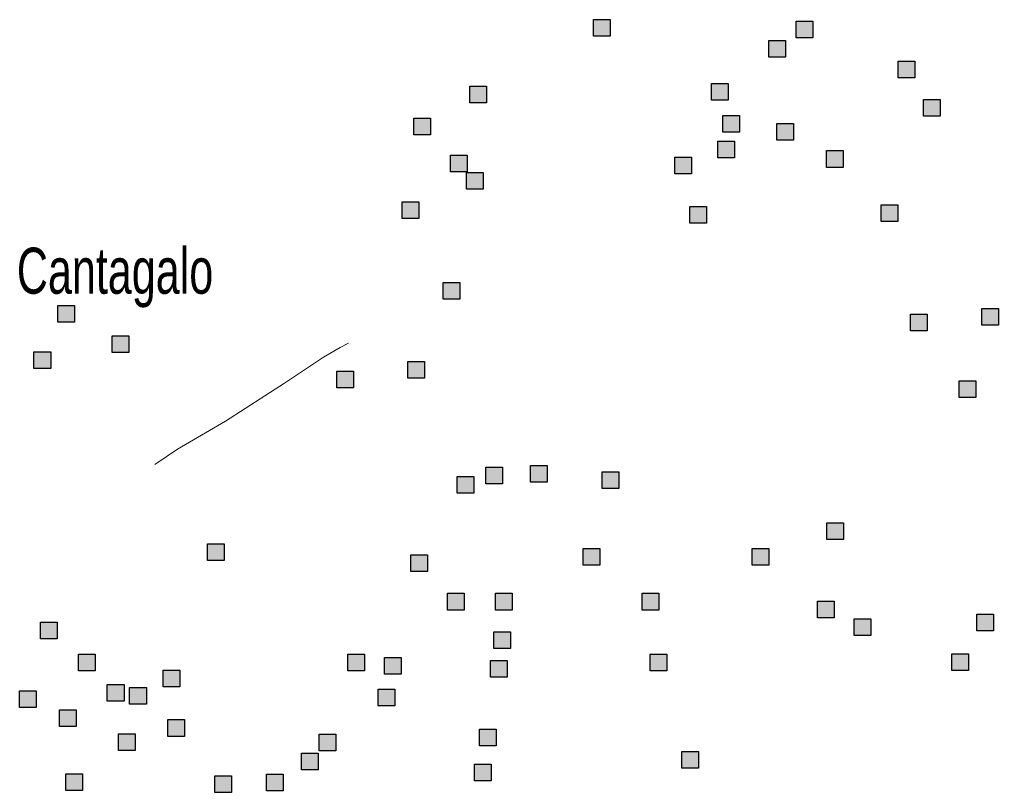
# Model space of a CAD drawing. Extents: x 445.6 to 500, y 8618.1 to 8673.4.
# Drawn here: x 476.597 to 479.999, y 8623.542 to 8626.229 of the extents above; entities that cross this region are included whole.
import ezdxf

# ---------------------------------------------------------------- set-up
doc = ezdxf.new("R2010")
doc.units = 0
doc.header["$LTSCALE"] = 0.064
doc.linetypes.add('DOT_DASHED', pattern=[7.7, 5, -1.2, 0.3, -1.2])
doc.layers.add('2', color=7, linetype='Continuous', lineweight=25)
doc.layers.add('22', color=7, linetype='DOT_DASHED', lineweight=13)
doc.layers.add('61', color=7, linetype='Continuous')

msp = doc.modelspace()

# ---------------------------------------------------------------- hatches: boundary and pattern name
at = {"layer": '2'}
for points in [[(478.592, 8626.2293), (478.65, 8626.2293), (478.65, 8626.1713), (478.592, 8626.1713)], [(479.2958, 8626.2237), (479.3538, 8626.2237), (479.3538, 8626.1657), (479.2958, 8626.1657)], [(479.2016, 8626.157), (479.2596, 8626.157), (479.2596, 8626.099), (479.2016, 8626.099)], [(479.6504, 8626.0848), (479.7084, 8626.0848), (479.7084, 8626.0268), (479.6504, 8626.0268)], [(479.0021, 8626.007), (479.0601, 8626.007), (479.0601, 8625.949), (479.0021, 8625.949)], [(478.1614, 8625.9974), (478.2194, 8625.9974), (478.2194, 8625.9394), (478.1614, 8625.9394)], [(479.7391, 8625.9514), (479.7971, 8625.9514), (479.7971, 8625.8934), (479.7391, 8625.8934)], [(477.9674, 8625.8863), (478.0254, 8625.8863), (478.0254, 8625.8283), (477.9674, 8625.8283)], [(479.0408, 8625.8958), (479.0988, 8625.8958), (479.0988, 8625.8378), (479.0408, 8625.8378)], [(479.2293, 8625.868), (479.2873, 8625.868), (479.2873, 8625.81), (479.2293, 8625.81)], [(479.0242, 8625.8069), (479.0822, 8625.8069), (479.0822, 8625.7489), (479.0242, 8625.7489)], [(479.4011, 8625.7735), (479.4591, 8625.7735), (479.4591, 8625.7155), (479.4011, 8625.7155)], [(478.0949, 8625.7584), (478.1529, 8625.7584), (478.1529, 8625.7004), (478.0949, 8625.7004)], [(478.8746, 8625.7513), (478.9326, 8625.7513), (478.9326, 8625.6933), (478.8746, 8625.6933)], [(478.1503, 8625.6973), (478.2083, 8625.6973), (478.2083, 8625.6393), (478.1503, 8625.6393)], [(477.9264, 8625.5959), (477.9844, 8625.5959), (477.9844, 8625.5379), (477.9264, 8625.5379)], [(478.9262, 8625.5795), (478.9842, 8625.5795), (478.9842, 8625.5215), (478.9262, 8625.5215)], [(479.5912, 8625.585), (479.6492, 8625.585), (479.6492, 8625.527), (479.5912, 8625.527)], [(478.0688, 8625.3154), (478.1268, 8625.3154), (478.1268, 8625.2574), (478.0688, 8625.2574)], [(476.7302, 8625.235), (476.7882, 8625.235), (476.7882, 8625.177), (476.7302, 8625.177)], [(479.9412, 8625.2246), (479.9992, 8625.2246), (479.9992, 8625.1666), (479.9412, 8625.1666)], [(479.6931, 8625.2045), (479.7511, 8625.2045), (479.7511, 8625.1465), (479.6931, 8625.1465)], [(476.9186, 8625.1294), (476.9766, 8625.1294), (476.9766, 8625.0714), (476.9186, 8625.0714)], [(476.6471, 8625.0738), (476.7051, 8625.0738), (476.7051, 8625.0158), (476.6471, 8625.0158)], [(477.9459, 8625.0403), (478.0039, 8625.0403), (478.0039, 8624.9823), (477.9459, 8624.9823)], [(477.6992, 8625.0068), (477.7572, 8625.0068), (477.7572, 8624.9488), (477.6992, 8624.9488)], [(479.8627, 8624.9736), (479.9207, 8624.9736), (479.9207, 8624.9156), (479.8627, 8624.9156)], [(478.2174, 8624.6735), (478.2754, 8624.6735), (478.2754, 8624.6155), (478.2174, 8624.6155)], [(478.3726, 8624.679), (478.4306, 8624.679), (478.4306, 8624.621), (478.3726, 8624.621)], [(478.6219, 8624.6568), (478.6799, 8624.6568), (478.6799, 8624.5988), (478.6219, 8624.5988)], [(478.1177, 8624.6401), (478.1757, 8624.6401), (478.1757, 8624.5821), (478.1177, 8624.5821)], [(479.4033, 8624.479), (479.4613, 8624.479), (479.4613, 8624.421), (479.4033, 8624.421)], [(477.2504, 8624.4065), (477.3084, 8624.4065), (477.3084, 8624.3485), (477.2504, 8624.3485)], [(478.5554, 8624.39), (478.6134, 8624.39), (478.6134, 8624.332), (478.5554, 8624.332)], [(479.1429, 8624.39), (479.2009, 8624.39), (479.2009, 8624.332), (479.1429, 8624.332)], [(477.9569, 8624.3678), (478.0149, 8624.3678), (478.0149, 8624.3098), (477.9569, 8624.3098)], [(478.0844, 8624.2344), (478.1424, 8624.2344), (478.1424, 8624.1764), (478.0844, 8624.1764)], [(478.2507, 8624.2344), (478.3087, 8624.2344), (478.3087, 8624.1764), (478.2507, 8624.1764)], [(478.7605, 8624.2344), (478.8185, 8624.2344), (478.8185, 8624.1764), (478.7605, 8624.1764)], [(479.3701, 8624.2066), (479.4281, 8624.2066), (479.4281, 8624.1486), (479.3701, 8624.1486)], [(479.4975, 8624.1455), (479.5555, 8624.1455), (479.5555, 8624.0875), (479.4975, 8624.0875)], [(479.9237, 8624.1621), (479.9817, 8624.1621), (479.9817, 8624.1041), (479.9237, 8624.1041)], [(476.6692, 8624.1345), (476.7272, 8624.1345), (476.7272, 8624.0765), (476.6692, 8624.0765)], [(478.2451, 8624.101), (478.3031, 8624.101), (478.3031, 8624.043), (478.2451, 8624.043)], [(476.8022, 8624.0233), (476.8602, 8624.0233), (476.8602, 8623.9653), (476.8022, 8623.9653)], [(477.738, 8624.023), (477.796, 8624.023), (477.796, 8623.965), (477.738, 8623.965)], [(477.8655, 8624.0118), (477.9235, 8624.0118), (477.9235, 8623.9538), (477.8655, 8623.9538)], [(478.234, 8624.001), (478.292, 8624.001), (478.292, 8623.943), (478.234, 8623.943)], [(478.7882, 8624.0232), (478.8462, 8624.0232), (478.8462, 8623.9652), (478.7882, 8623.9652)], [(479.8369, 8624.0237), (479.8949, 8624.0237), (479.8949, 8623.9657), (479.8369, 8623.9657)], [(477.0959, 8623.9677), (477.1539, 8623.9677), (477.1539, 8623.9097), (477.0959, 8623.9097)], [(476.902, 8623.9177), (476.96, 8623.9177), (476.96, 8623.8597), (476.902, 8623.8597)], [(476.9796, 8623.9066), (477.0376, 8623.9066), (477.0376, 8623.8486), (476.9796, 8623.8486)], [(477.8433, 8623.9007), (477.9013, 8623.9007), (477.9013, 8623.8427), (477.8433, 8623.8427)], [(476.5972, 8623.8955), (476.6552, 8623.8955), (476.6552, 8623.8375), (476.5972, 8623.8375)], [(476.7357, 8623.8288), (476.7937, 8623.8288), (476.7937, 8623.7708), (476.7357, 8623.7708)], [(477.1118, 8623.7951), (477.1698, 8623.7951), (477.1698, 8623.7371), (477.1118, 8623.7371)], [(478.1952, 8623.762), (478.2532, 8623.762), (478.2532, 8623.704), (478.1952, 8623.704)], [(476.9408, 8623.7454), (476.9988, 8623.7454), (476.9988, 8623.6874), (476.9408, 8623.6874)], [(477.6383, 8623.7451), (477.6963, 8623.7451), (477.6963, 8623.6871), (477.6383, 8623.6871)], [(477.5773, 8623.6784), (477.6353, 8623.6784), (477.6353, 8623.6204), (477.5773, 8623.6204)], [(478.899, 8623.6841), (478.957, 8623.6841), (478.957, 8623.6261), (478.899, 8623.6261)], [(478.1786, 8623.6405), (478.2366, 8623.6405), (478.2366, 8623.5825), (478.1786, 8623.5825)], [(476.7579, 8623.6064), (476.8159, 8623.6064), (476.8159, 8623.5484), (476.7579, 8623.5484)], [(477.2752, 8623.6001), (477.3332, 8623.6001), (477.3332, 8623.5421), (477.2752, 8623.5421)], [(477.4554, 8623.6061), (477.5134, 8623.6061), (477.5134, 8623.5481), (477.4554, 8623.5481)]]:
    msp.add_hatch(color=256, dxfattribs=at).paths.add_polyline_path(points)

# ---------------------------------------------------------------- linework, layer by layer
for points in [[(478.592, 8626.2293), (478.65, 8626.2293), (478.65, 8626.1713), (478.592, 8626.1713)], [(479.2958, 8626.2237), (479.3538, 8626.2237), (479.3538, 8626.1657), (479.2958, 8626.1657)], [(479.2016, 8626.157), (479.2596, 8626.157), (479.2596, 8626.099), (479.2016, 8626.099)], [(479.6504, 8626.0848), (479.7084, 8626.0848), (479.7084, 8626.0268), (479.6504, 8626.0268)], [(479.0021, 8626.007), (479.0601, 8626.007), (479.0601, 8625.949), (479.0021, 8625.949)], [(478.1614, 8625.9974), (478.2194, 8625.9974), (478.2194, 8625.9394), (478.1614, 8625.9394)], [(479.7391, 8625.9514), (479.7971, 8625.9514), (479.7971, 8625.8934), (479.7391, 8625.8934)], [(477.9674, 8625.8863), (478.0254, 8625.8863), (478.0254, 8625.8283), (477.9674, 8625.8283)], [(479.0408, 8625.8958), (479.0988, 8625.8958), (479.0988, 8625.8378), (479.0408, 8625.8378)], [(479.2293, 8625.868), (479.2873, 8625.868), (479.2873, 8625.81), (479.2293, 8625.81)], [(479.0242, 8625.8069), (479.0822, 8625.8069), (479.0822, 8625.7489), (479.0242, 8625.7489)], [(479.4011, 8625.7735), (479.4591, 8625.7735), (479.4591, 8625.7155), (479.4011, 8625.7155)], [(478.0949, 8625.7584), (478.1529, 8625.7584), (478.1529, 8625.7004), (478.0949, 8625.7004)], [(478.8746, 8625.7513), (478.9326, 8625.7513), (478.9326, 8625.6933), (478.8746, 8625.6933)], [(478.1503, 8625.6973), (478.2083, 8625.6973), (478.2083, 8625.6393), (478.1503, 8625.6393)], [(477.9264, 8625.5959), (477.9844, 8625.5959), (477.9844, 8625.5379), (477.9264, 8625.5379)], [(478.9262, 8625.5795), (478.9842, 8625.5795), (478.9842, 8625.5215), (478.9262, 8625.5215)], [(479.5912, 8625.585), (479.6492, 8625.585), (479.6492, 8625.527), (479.5912, 8625.527)], [(478.0688, 8625.3154), (478.1268, 8625.3154), (478.1268, 8625.2574), (478.0688, 8625.2574)], [(476.7302, 8625.235), (476.7882, 8625.235), (476.7882, 8625.177), (476.7302, 8625.177)], [(479.9412, 8625.2246), (479.9992, 8625.2246), (479.9992, 8625.1666), (479.9412, 8625.1666)], [(479.6931, 8625.2045), (479.7511, 8625.2045), (479.7511, 8625.1465), (479.6931, 8625.1465)], [(476.9186, 8625.1294), (476.9766, 8625.1294), (476.9766, 8625.0714), (476.9186, 8625.0714)], [(476.6471, 8625.0738), (476.7051, 8625.0738), (476.7051, 8625.0158), (476.6471, 8625.0158)], [(477.9459, 8625.0403), (478.0039, 8625.0403), (478.0039, 8624.9823), (477.9459, 8624.9823)], [(477.6992, 8625.0068), (477.7572, 8625.0068), (477.7572, 8624.9488), (477.6992, 8624.9488)], [(479.8627, 8624.9736), (479.9207, 8624.9736), (479.9207, 8624.9156), (479.8627, 8624.9156)], [(478.2174, 8624.6735), (478.2754, 8624.6735), (478.2754, 8624.6155), (478.2174, 8624.6155)], [(478.3726, 8624.679), (478.4306, 8624.679), (478.4306, 8624.621), (478.3726, 8624.621)], [(478.6219, 8624.6568), (478.6799, 8624.6568), (478.6799, 8624.5988), (478.6219, 8624.5988)], [(478.1177, 8624.6401), (478.1757, 8624.6401), (478.1757, 8624.5821), (478.1177, 8624.5821)], [(479.4033, 8624.479), (479.4613, 8624.479), (479.4613, 8624.421), (479.4033, 8624.421)], [(477.2504, 8624.4065), (477.3084, 8624.4065), (477.3084, 8624.3485), (477.2504, 8624.3485)], [(478.5554, 8624.39), (478.6134, 8624.39), (478.6134, 8624.332), (478.5554, 8624.332)], [(479.1429, 8624.39), (479.2009, 8624.39), (479.2009, 8624.332), (479.1429, 8624.332)], [(477.9569, 8624.3678), (478.0149, 8624.3678), (478.0149, 8624.3098), (477.9569, 8624.3098)], [(478.0844, 8624.2344), (478.1424, 8624.2344), (478.1424, 8624.1764), (478.0844, 8624.1764)], [(478.2507, 8624.2344), (478.3087, 8624.2344), (478.3087, 8624.1764), (478.2507, 8624.1764)], [(478.7605, 8624.2344), (478.8185, 8624.2344), (478.8185, 8624.1764), (478.7605, 8624.1764)], [(479.3701, 8624.2066), (479.4281, 8624.2066), (479.4281, 8624.1486), (479.3701, 8624.1486)], [(479.4975, 8624.1455), (479.5555, 8624.1455), (479.5555, 8624.0875), (479.4975, 8624.0875)], [(479.9237, 8624.1621), (479.9817, 8624.1621), (479.9817, 8624.1041), (479.9237, 8624.1041)], [(476.6692, 8624.1345), (476.7272, 8624.1345), (476.7272, 8624.0765), (476.6692, 8624.0765)], [(478.2451, 8624.101), (478.3031, 8624.101), (478.3031, 8624.043), (478.2451, 8624.043)], [(476.8022, 8624.0233), (476.8602, 8624.0233), (476.8602, 8623.9653), (476.8022, 8623.9653)], [(477.738, 8624.023), (477.796, 8624.023), (477.796, 8623.965), (477.738, 8623.965)], [(477.8655, 8624.0118), (477.9235, 8624.0118), (477.9235, 8623.9538), (477.8655, 8623.9538)], [(478.234, 8624.001), (478.292, 8624.001), (478.292, 8623.943), (478.234, 8623.943)], [(478.7882, 8624.0232), (478.8462, 8624.0232), (478.8462, 8623.9652), (478.7882, 8623.9652)], [(479.8369, 8624.0237), (479.8949, 8624.0237), (479.8949, 8623.9657), (479.8369, 8623.9657)], [(477.0959, 8623.9677), (477.1539, 8623.9677), (477.1539, 8623.9097), (477.0959, 8623.9097)], [(476.902, 8623.9177), (476.96, 8623.9177), (476.96, 8623.8597), (476.902, 8623.8597)], [(476.9796, 8623.9066), (477.0376, 8623.9066), (477.0376, 8623.8486), (476.9796, 8623.8486)], [(477.8433, 8623.9007), (477.9013, 8623.9007), (477.9013, 8623.8427), (477.8433, 8623.8427)], [(476.5972, 8623.8955), (476.6552, 8623.8955), (476.6552, 8623.8375), (476.5972, 8623.8375)], [(476.7357, 8623.8288), (476.7937, 8623.8288), (476.7937, 8623.7708), (476.7357, 8623.7708)], [(477.1118, 8623.7951), (477.1698, 8623.7951), (477.1698, 8623.7371), (477.1118, 8623.7371)], [(478.1952, 8623.762), (478.2532, 8623.762), (478.2532, 8623.704), (478.1952, 8623.704)], [(476.9408, 8623.7454), (476.9988, 8623.7454), (476.9988, 8623.6874), (476.9408, 8623.6874)], [(477.6383, 8623.7451), (477.6963, 8623.7451), (477.6963, 8623.6871), (477.6383, 8623.6871)], [(477.5773, 8623.6784), (477.6353, 8623.6784), (477.6353, 8623.6204), (477.5773, 8623.6204)], [(478.899, 8623.6841), (478.957, 8623.6841), (478.957, 8623.6261), (478.899, 8623.6261)], [(478.1786, 8623.6405), (478.2366, 8623.6405), (478.2366, 8623.5825), (478.1786, 8623.5825)], [(476.7579, 8623.6064), (476.8159, 8623.6064), (476.8159, 8623.5484), (476.7579, 8623.5484)], [(477.2752, 8623.6001), (477.3332, 8623.6001), (477.3332, 8623.5421), (477.2752, 8623.5421)], [(477.4554, 8623.6061), (477.5134, 8623.6061), (477.5134, 8623.5481), (477.4554, 8623.5481)]]:
    msp.add_lwpolyline(points, close=True, dxfattribs=at)
at = {"layer": '22'}
msp.add_lwpolyline([(477.0667, 8624.6818), (477.1461, 8624.7358), (477.3122, 8624.8324), (477.5183, 8624.9647), (477.6529, 8625.055), (477.7117, 8625.0886), (477.7398, 8625.1037)], dxfattribs=at)

# ---------------------------------------------------------------- texts
at = {"layer": '61', "width": 0.7}
msp.add_text('Faz. Cantagalo', height=0.16, dxfattribs=at).set_placement((476.2545, 8625.2761))

doc.saveas('drawing.dxf')
